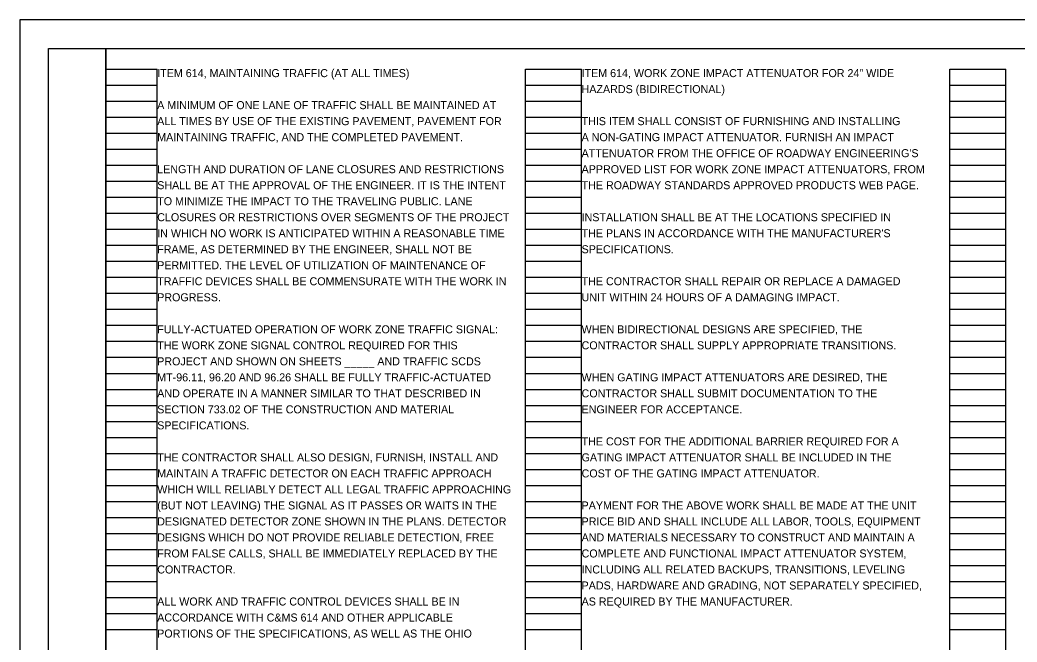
# Model space of a CAD drawing. Extents: x 0 to 59.9, y -1.6 to 22.
# Drawn here: x 0 to 17.43, y 11.12 to 22 of the extents above; entities that cross this region are included whole.
import ezdxf

# ---------------------------------------------------------------- set-up
doc = ezdxf.new("R2010")
doc.units = 0
for name, color, linetype in [('SH_Border', 7, 'Continuous'), ('SH_Cut_Line', 7, 'Continuous'), ('SH_Data', 7, 'Continuous'), ('SH_Text', 7, 'Continuous')]:
    doc.layers.add(name, color=color, linetype=linetype)

msp = doc.modelspace()

# ---------------------------------------------------------------- linework, layer by layer
at = {"layer": 'SH_Border'}
for points in [[(0.5, 21.5), (1.5, 21.5), (1.5, 0.5), (0.5, 0.5)], [(1.5, 21.5), (33.5, 21.5), (33.5, 0.5), (1.5, 0.5)]]:
    msp.add_lwpolyline(points, close=True, dxfattribs=at)
at = {"layer": 'SH_Cut_Line'}
msp.add_lwpolyline([(0, 0), (34, 0), (34, 22), (0, 22)], close=True, dxfattribs=at)
at = {"layer": 'SH_Data'}
for p, q in [((1.5, 0.98), (1.5, 21.14)), ((1.5, 21.14), (2.4, 21.14)), ((2.4, 0.98), (2.4, 21.14)), ((8.84, 0.98), (8.84, 21.14)), ((8.84, 21.14), (9.82, 21.14)), ((9.82, 0.98), (9.82, 21.14)), ((16.26, 0.98), (16.26, 21.14)), ((16.26, 21.14), (17.24, 21.14)), ((17.24, 0.98), (17.24, 21.14)), ((1.5, 20.86), (2.4, 20.86)), ((8.84, 20.86), (9.82, 20.86)), ((16.26, 20.86), (17.24, 20.86)), ((1.5, 20.58), (2.4, 20.58)), ((8.84, 20.58), (9.82, 20.58)), ((16.26, 20.58), (17.24, 20.58)), ((1.5, 20.3), (2.4, 20.3)), ((8.84, 20.3), (9.82, 20.3)), ((16.26, 20.3), (17.24, 20.3)), ((1.5, 20.02), (2.4, 20.02)), ((8.84, 20.02), (9.82, 20.02)), ((16.26, 20.02), (17.24, 20.02)), ((1.5, 19.74), (2.4, 19.74)), ((8.84, 19.74), (9.82, 19.74)), ((16.26, 19.74), (17.24, 19.74)), ((1.5, 19.46), (2.4, 19.46)), ((8.84, 19.46), (9.82, 19.46)), ((16.26, 19.46), (17.24, 19.46)), ((1.5, 19.18), (2.4, 19.18)), ((8.84, 19.18), (9.82, 19.18)), ((16.26, 19.18), (17.24, 19.18)), ((1.5, 18.9), (2.4, 18.9)), ((8.84, 18.9), (9.82, 18.9)), ((16.26, 18.9), (17.24, 18.9)), ((1.5, 18.62), (2.4, 18.62)), ((8.84, 18.62), (9.82, 18.62)), ((16.26, 18.62), (17.24, 18.62)), ((1.5, 18.34), (2.4, 18.34)), ((8.84, 18.34), (9.82, 18.34)), ((16.26, 18.34), (17.24, 18.34)), ((1.5, 18.06), (2.4, 18.06)), ((8.84, 18.06), (9.82, 18.06)), ((16.26, 18.06), (17.24, 18.06)), ((1.5, 17.78), (2.4, 17.78)), ((8.84, 17.78), (9.82, 17.78)), ((16.26, 17.78), (17.24, 17.78)), ((1.5, 17.5), (2.4, 17.5)), ((8.84, 17.5), (9.82, 17.5)), ((16.26, 17.5), (17.24, 17.5)), ((1.5, 17.22), (2.4, 17.22)), ((8.84, 17.22), (9.82, 17.22)), ((16.26, 17.22), (17.24, 17.22)), ((1.5, 16.94), (2.4, 16.94)), ((8.84, 16.94), (9.82, 16.94)), ((16.26, 16.94), (17.24, 16.94)), ((1.5, 16.66), (2.4, 16.66)), ((8.84, 16.66), (9.82, 16.66)), ((16.26, 16.66), (17.24, 16.66)), ((1.5, 16.38), (2.4, 16.38)), ((8.84, 16.38), (9.82, 16.38)), ((16.26, 16.38), (17.24, 16.38)), ((1.5, 16.1), (2.4, 16.1)), ((8.84, 16.1), (9.82, 16.1)), ((16.26, 16.1), (17.24, 16.1)), ((1.5, 15.82), (2.4, 15.82)), ((8.84, 15.82), (9.82, 15.82)), ((16.26, 15.82), (17.24, 15.82)), ((1.5, 15.54), (2.4, 15.54)), ((8.84, 15.54), (9.82, 15.54)), ((16.26, 15.54), (17.24, 15.54)), ((1.5, 15.26), (2.4, 15.26)), ((8.84, 15.26), (9.82, 15.26)), ((16.26, 15.26), (17.24, 15.26)), ((1.5, 14.98), (2.4, 14.98)), ((8.84, 14.98), (9.82, 14.98)), ((16.26, 14.98), (17.24, 14.98)), ((1.5, 14.7), (2.4, 14.7)), ((8.84, 14.7), (9.82, 14.7)), ((16.26, 14.7), (17.24, 14.7)), ((1.5, 14.42), (2.4, 14.42)), ((8.84, 14.42), (9.82, 14.42)), ((16.26, 14.42), (17.24, 14.42)), ((1.5, 14.14), (2.4, 14.14)), ((8.84, 14.14), (9.82, 14.14)), ((16.26, 14.14), (17.24, 14.14)), ((1.5, 13.86), (2.4, 13.86)), ((8.84, 13.86), (9.82, 13.86)), ((16.26, 13.86), (17.24, 13.86)), ((1.5, 13.58), (2.4, 13.58)), ((8.84, 13.58), (9.82, 13.58)), ((16.26, 13.58), (17.24, 13.58)), ((1.5, 13.3), (2.4, 13.3)), ((8.84, 13.3), (9.82, 13.3)), ((16.26, 13.3), (17.24, 13.3)), ((1.5, 13.02), (2.4, 13.02)), ((8.84, 13.02), (9.82, 13.02)), ((16.26, 13.02), (17.24, 13.02)), ((1.5, 12.74), (2.4, 12.74)), ((8.84, 12.74), (9.82, 12.74)), ((16.26, 12.74), (17.24, 12.74)), ((1.5, 12.46), (2.4, 12.46)), ((8.84, 12.46), (9.82, 12.46)), ((16.26, 12.46), (17.24, 12.46)), ((1.5, 12.18), (2.4, 12.18)), ((8.84, 12.18), (9.82, 12.18)), ((16.26, 12.18), (17.24, 12.18)), ((1.5, 11.9), (2.4, 11.9)), ((8.84, 11.9), (9.82, 11.9)), ((16.26, 11.9), (17.24, 11.9)), ((1.5, 11.62), (2.4, 11.62)), ((8.84, 11.62), (9.82, 11.62)), ((16.26, 11.62), (17.24, 11.62)), ((1.5, 11.34), (2.4, 11.34)), ((8.84, 11.34), (9.82, 11.34)), ((16.26, 11.34), (17.24, 11.34))]:
    msp.add_line(p, q, dxfattribs=at)

# ---------------------------------------------------------------- texts
at = {"layer": 'SH_Text'}
for s, p in [('ITEM 614, MAINTAINING TRAFFIC (AT ALL TIMES)', (2.4, 21)), ('ITEM 614, WORK ZONE IMPACT ATTENUATOR FOR 24" WIDE', (9.82, 21)), ('HAZARDS (BIDIRECTIONAL)', (9.82, 20.72)), ('A MINIMUM OF ONE LANE OF TRAFFIC SHALL BE MAINTAINED AT ', (2.4, 20.44)), ('ALL TIMES BY USE OF THE EXISTING PAVEMENT, PAVEMENT FOR ', (2.4, 20.16)), ('THIS ITEM SHALL CONSIST OF FURNISHING AND INSTALLING', (9.82, 20.16)), ('MAINTAINING TRAFFIC, AND THE COMPLETED PAVEMENT.', (2.4, 19.88)), ('A NON-GATING IMPACT ATTENUATOR. FURNISH AN IMPACT', (9.82, 19.88)), ("ATTENUATOR FROM THE OFFICE OF ROADWAY ENGINEERING'S", (9.82, 19.6)), ('LENGTH AND DURATION OF LANE CLOSURES AND RESTRICTIONS', (2.4, 19.32)), ('APPROVED LIST FOR WORK ZONE IMPACT ATTENUATORS, FROM', (9.82, 19.32)), ('SHALL BE AT THE APPROVAL OF THE ENGINEER. IT IS THE INTENT', (2.4, 19.04)), ('THE ROADWAY STANDARDS APPROVED PRODUCTS WEB PAGE.', (9.82, 19.04)), ('TO MINIMIZE THE IMPACT TO THE TRAVELING PUBLIC. LANE', (2.4, 18.76)), ('CLOSURES OR RESTRICTIONS OVER SEGMENTS OF THE PROJECT', (2.4, 18.48)), ('INSTALLATION SHALL BE AT THE LOCATIONS SPECIFIED IN', (9.82, 18.48)), ('IN WHICH NO WORK IS ANTICIPATED WITHIN A REASONABLE TIME', (2.4, 18.2)), ("THE PLANS IN ACCORDANCE WITH THE MANUFACTURER'S", (9.82, 18.2)), ('FRAME, AS DETERMINED BY THE ENGINEER, SHALL NOT BE', (2.4, 17.92)), ('SPECIFICATIONS.', (9.82, 17.92)), ('PERMITTED. THE LEVEL OF UTILIZATION OF MAINTENANCE OF', (2.4, 17.64)), ('TRAFFIC DEVICES SHALL BE COMMENSURATE WITH THE WORK IN', (2.4, 17.36)), ('THE CONTRACTOR SHALL REPAIR OR REPLACE A DAMAGED', (9.82, 17.36)), ('PROGRESS.', (2.4, 17.08)), ('UNIT WITHIN 24 HOURS OF A DAMAGING IMPACT.', (9.82, 17.08)), ('FULLY-ACTUATED OPERATION OF WORK ZONE TRAFFIC SIGNAL:', (2.4, 16.52)), ('WHEN BIDIRECTIONAL DESIGNS ARE SPECIFIED, THE', (9.82, 16.52)), ('THE WORK ZONE SIGNAL CONTROL REQUIRED FOR THIS', (2.4, 16.24)), ('CONTRACTOR SHALL SUPPLY APPROPRIATE TRANSITIONS.', (9.82, 16.24)), ('PROJECT AND SHOWN ON SHEETS _____ AND TRAFFIC SCDS', (2.4, 15.96)), ('MT-96.11, 96.20 AND 96.26 SHALL BE FULLY TRAFFIC-ACTUATED', (2.4, 15.68)), ('WHEN GATING IMPACT ATTENUATORS ARE DESIRED, THE', (9.82, 15.68)), ('AND OPERATE IN A MANNER SIMILAR TO THAT DESCRIBED IN', (2.4, 15.4)), ('CONTRACTOR SHALL SUBMIT DOCUMENTATION TO THE', (9.82, 15.4)), ('SECTION 733.02 OF THE CONSTRUCTION AND MATERIAL', (2.4, 15.12)), ('ENGINEER FOR ACCEPTANCE.', (9.82, 15.12)), ('SPECIFICATIONS.', (2.4, 14.84)), ('THE COST FOR THE ADDITIONAL BARRIER REQUIRED FOR A', (9.82, 14.56)), ('THE CONTRACTOR SHALL ALSO DESIGN, FURNISH, INSTALL AND', (2.4, 14.28)), ('GATING IMPACT ATTENUATOR SHALL BE INCLUDED IN THE', (9.82, 14.28)), ('MAINTAIN A TRAFFIC DETECTOR ON EACH TRAFFIC APPROACH', (2.4, 14)), ('COST OF THE GATING IMPACT ATTENUATOR.', (9.82, 14)), ('WHICH WILL RELIABLY DETECT ALL LEGAL TRAFFIC APPROACHING', (2.4, 13.72)), ('(BUT NOT LEAVING) THE SIGNAL AS IT PASSES OR WAITS IN THE', (2.4, 13.44)), ('PAYMENT FOR THE ABOVE WORK SHALL BE MADE AT THE UNIT', (9.82, 13.44)), ('DESIGNATED DETECTOR ZONE SHOWN IN THE PLANS. DETECTOR', (2.4, 13.16)), ('PRICE BID AND SHALL INCLUDE ALL LABOR, TOOLS, EQUIPMENT', (9.82, 13.16)), ('DESIGNS WHICH DO NOT PROVIDE RELIABLE DETECTION, FREE', (2.4, 12.88)), ('AND MATERIALS NECESSARY TO CONSTRUCT AND MAINTAIN A', (9.82, 12.88)), ('FROM FALSE CALLS, SHALL BE IMMEDIATELY REPLACED BY THE', (2.4, 12.6)), ('COMPLETE AND FUNCTIONAL IMPACT ATTENUATOR SYSTEM,', (9.82, 12.6)), ('CONTRACTOR.', (2.4, 12.32)), ('INCLUDING ALL RELATED BACKUPS, TRANSITIONS, LEVELING', (9.82, 12.32)), ('PADS, HARDWARE AND GRADING, NOT SEPARATELY SPECIFIED,', (9.82, 12.04)), ('ALL WORK AND TRAFFIC CONTROL DEVICES SHALL BE IN', (2.4, 11.76)), ('AS REQUIRED BY THE MANUFACTURER.', (9.82, 11.76)), ('ACCORDANCE WITH C&MS 614 AND OTHER APPLICABLE', (2.4, 11.48)), ('PORTIONS OF THE SPECIFICATIONS, AS WELL AS THE OHIO', (2.4, 11.2))]:
    msp.add_text(s, height=0.14, dxfattribs=at).set_placement(p)

doc.saveas('drawing.dxf')
